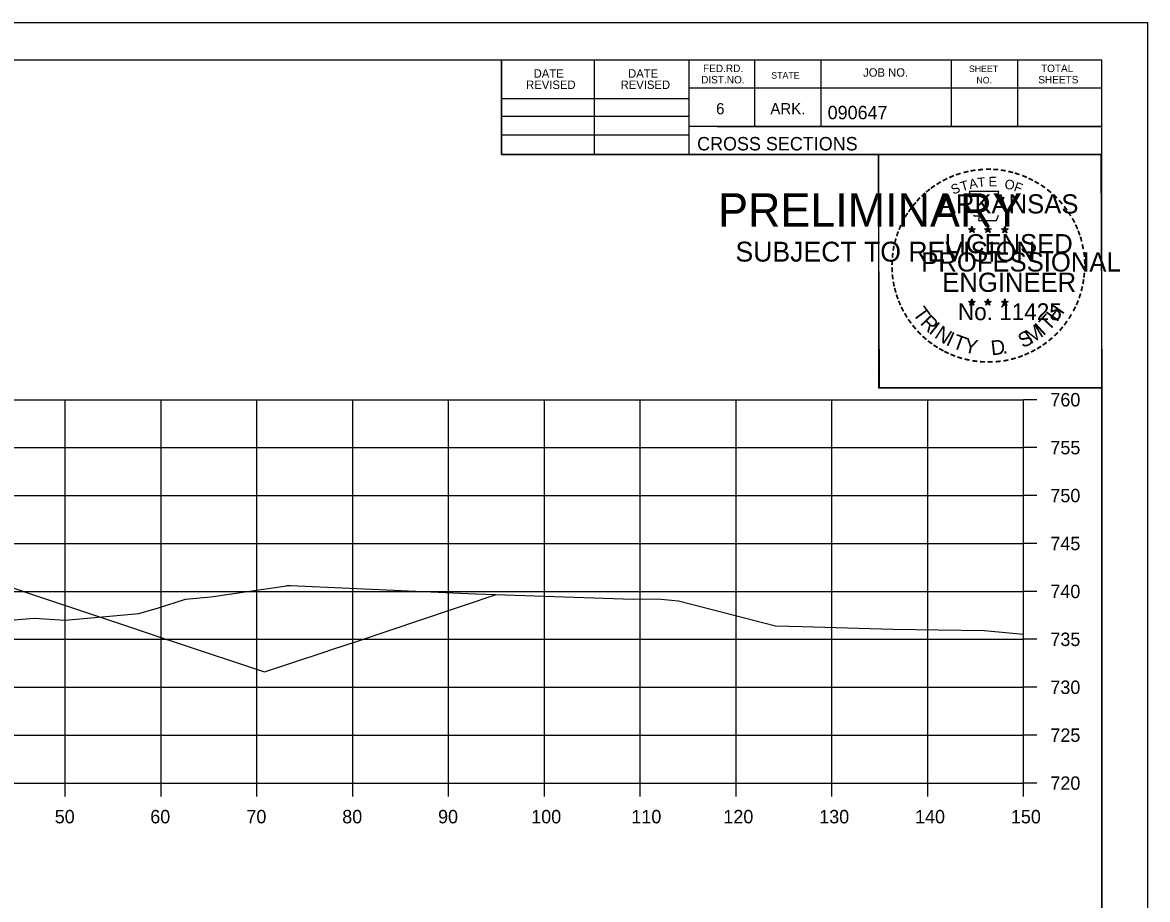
# Model space of a CAD drawing. Extents: x 1202951 to 1376887, y 378065 to 728038.
# Drawn here: x 1374330.5 to 1374447.9, y 379095.1 to 379186.6 of the extents above; entities that cross this region are included whole.
import ezdxf

# ---------------------------------------------------------------- set-up
doc = ezdxf.new("R2010")
doc.units = 0
for name, color, linetype in [('R_Axis', 7, 'Continuous'), ('R_Axis Annot', 7, 'Continuous'), ('R_Exist Surface', 7, 'Continuous'), ('R_Fin Surface', 7, 'Continuous'), ('R_Grid', 7, 'Continuous'), ('R_No Plot', 7, 'Continuous')]:
    doc.layers.add(name, color=color, linetype=linetype)

msp = doc.modelspace()

# ---------------------------------------------------------------- linework, layer by layer
at = {"layer": 'R_Axis'}
for p, q in [((1374434.98, 379107.26), (1374434.98, 379147.26)), ((1374436.38, 379147.26), (1374434.98, 379147.26)), ((1374436.38, 379142.26), (1374434.98, 379142.26)), ((1374436.38, 379137.26), (1374434.98, 379137.26)), ((1374436.38, 379132.26), (1374434.98, 379132.26)), ((1374436.38, 379127.26), (1374434.98, 379127.26)), ((1374436.38, 379122.26), (1374434.98, 379122.26)), ((1374436.38, 379117.26), (1374434.98, 379117.26)), ((1374436.38, 379112.26), (1374434.98, 379112.26)), ((1374134.98, 379107.26), (1374434.98, 379107.26)), ((1374334.98, 379105.86), (1374334.98, 379107.26)), ((1374344.98, 379105.86), (1374344.98, 379107.26)), ((1374354.98, 379105.86), (1374354.98, 379107.26)), ((1374364.98, 379105.86), (1374364.98, 379107.26)), ((1374374.98, 379105.86), (1374374.98, 379107.26)), ((1374384.98, 379105.86), (1374384.98, 379107.26)), ((1374394.98, 379105.86), (1374394.98, 379107.26)), ((1374404.98, 379105.86), (1374404.98, 379107.26)), ((1374414.98, 379105.86), (1374414.98, 379107.26)), ((1374424.98, 379105.86), (1374424.98, 379107.26)), ((1374434.98, 379105.86), (1374434.98, 379107.26)), ((1374436.38, 379107.26), (1374434.98, 379107.26))]:
    msp.add_line(p, q, dxfattribs=at)
at = {"layer": 'R_Exist Surface'}
msp.add_lwpolyline([(1374327.13, 379124.08), (1374331.76, 379124.46), (1374334.98, 379124.26), (1374342.65, 379124.96), (1374344.7, 379125.55), (1374347.52, 379126.45), (1374350.18, 379126.69), (1374358.08, 379127.85), (1374358.16, 379127.86), (1374358.49, 379127.89), (1374370.8, 379127.32), (1374377.81, 379126.99), (1374394.26, 379126.44), (1374396.79, 379126.47), (1374398.99, 379126.28), (1374409.09, 379123.66), (1374411.88, 379123.59), (1374421.33, 379123.32), (1374430.87, 379123.19), (1374434.98, 379122.81)], dxfattribs=at)
at = {"layer": 'R_Fin Surface'}
msp.add_lwpolyline([(1374319.78, 379130.87), (1374341.6, 379123.59), (1374345.29, 379122.36), (1374346.34, 379122.01), (1374355.78, 379118.86), (1374361.9, 379120.9), (1374362.9, 379121.23), (1374365.36, 379122.05), (1374375.6, 379125.47), (1374375.9, 379125.57), (1374376.63, 379125.81), (1374379.96, 379126.92)], dxfattribs=at)
at = {"layer": 'R_Grid'}
for p, q in [((1374134.98, 379147.26), (1374434.98, 379147.26)), ((1374334.98, 379107.26), (1374334.98, 379147.26)), ((1374344.98, 379107.26), (1374344.98, 379147.26)), ((1374354.98, 379107.26), (1374354.98, 379147.26)), ((1374364.98, 379107.26), (1374364.98, 379147.26)), ((1374374.98, 379107.26), (1374374.98, 379147.26)), ((1374384.98, 379107.26), (1374384.98, 379147.26)), ((1374394.98, 379107.26), (1374394.98, 379147.26)), ((1374404.98, 379107.26), (1374404.98, 379147.26)), ((1374414.98, 379107.26), (1374414.98, 379147.26)), ((1374424.98, 379107.26), (1374424.98, 379147.26)), ((1374434.98, 379107.26), (1374434.98, 379147.26)), ((1374134.98, 379142.26), (1374434.98, 379142.26)), ((1374134.98, 379137.26), (1374434.98, 379137.26)), ((1374134.98, 379132.26), (1374434.98, 379132.26)), ((1374134.98, 379127.26), (1374434.98, 379127.26)), ((1374134.98, 379122.26), (1374434.98, 379122.26)), ((1374134.98, 379117.26), (1374434.98, 379117.26)), ((1374134.98, 379112.26), (1374434.98, 379112.26)), ((1374134.98, 379107.26), (1374434.98, 379107.26))]:
    msp.add_line(p, q, dxfattribs=at)
at = {"layer": 'R_No Plot'}
for p, q in [((1374114.58, 379186.62), (1374447.91, 379186.62)), ((1374126.98, 379182.72), (1374443.16, 379182.72)), ((1374380.52, 379172.84), (1374380.52, 379182.72)), ((1374390.2, 379172.84), (1374390.2, 379182.72)), ((1374400.06, 379182.72), (1374400.06, 379172.84)), ((1374406.9, 379182.72), (1374406.9, 379175.78)), ((1374413.84, 379182.72), (1374413.84, 379175.78)), ((1374427.42, 379182.72), (1374427.42, 379175.78)), ((1374434.36, 379182.72), (1374434.36, 379175.78)), ((1374443.16, 378977.26), (1374443.16, 379182.72)), ((1374443.16, 379179.78), (1374400.06, 379179.78)), ((1374443.16, 379179.8), (1374443.16, 379179.8)), ((1374380.52, 379178.7), (1374400.06, 379178.7)), ((1374380.52, 379176.84), (1374400.06, 379176.84)), ((1374443.16, 379175.78), (1374400.06, 379175.78)), ((1374403.02, 379175.78), (1374443.16, 379175.78)), ((1374380.52, 379174.9), (1374400.06, 379174.9)), ((1374443.16, 379172.84), (1374380.52, 379172.84)), ((1374429.24, 379165.1), (1374429.59, 379164.98)), ((1374429.24, 379165.1), (1374429.5, 379165.05)), ((1374429.24, 379165.1), (1374429.48, 379164.97)), ((1374429.38, 379164.69), (1374429.59, 379164.98)), ((1374429.38, 379164.69), (1374429.5, 379164.93)), ((1374429.38, 379164.69), (1374429.59, 379164.9)), ((1374429.59, 379165.35), (1374429.55, 379165.1)), ((1374429.59, 379164.98), (1374429.59, 379165.35)), ((1374429.59, 379165.35), (1374429.64, 379165.1)), ((1374429.94, 379165.1), (1374429.59, 379164.98)), ((1374429.81, 379164.69), (1374429.59, 379164.98)), ((1374429.81, 379164.69), (1374429.59, 379164.9)), ((1374429.94, 379165.1), (1374429.65, 379165.05)), ((1374429.81, 379164.69), (1374429.67, 379164.98)), ((1374429.94, 379165.1), (1374429.74, 379164.99)), ((1374430.91, 379165.1), (1374431.26, 379164.98)), ((1374430.91, 379165.1), (1374431.17, 379165.05)), ((1374430.91, 379165.1), (1374431.15, 379164.97)), ((1374431.05, 379164.69), (1374431.26, 379164.98)), ((1374431.05, 379164.69), (1374431.17, 379164.93)), ((1374431.05, 379164.69), (1374431.26, 379164.9)), ((1374431.26, 379165.35), (1374431.22, 379165.1)), ((1374431.26, 379164.98), (1374431.26, 379165.35)), ((1374431.26, 379165.35), (1374431.31, 379165.1)), ((1374431.61, 379165.1), (1374431.26, 379164.98)), ((1374431.48, 379164.69), (1374431.26, 379164.98)), ((1374431.48, 379164.69), (1374431.26, 379164.9)), ((1374431.61, 379165.1), (1374431.32, 379165.05)), ((1374431.48, 379164.69), (1374431.34, 379164.98)), ((1374431.61, 379165.1), (1374431.41, 379164.99)), ((1374432.68, 379165.08), (1374433.03, 379164.97)), ((1374432.68, 379165.08), (1374432.93, 379165.04)), ((1374432.68, 379165.08), (1374432.92, 379164.96)), ((1374432.81, 379164.68), (1374433.03, 379164.97)), ((1374432.81, 379164.68), (1374432.94, 379164.92)), ((1374432.81, 379164.68), (1374433.03, 379164.89)), ((1374433.03, 379165.34), (1374432.99, 379165.09)), ((1374433.03, 379164.97), (1374433.03, 379165.34)), ((1374433.03, 379165.34), (1374433.08, 379165.09)), ((1374433.37, 379165.08), (1374433.03, 379164.97)), ((1374433.24, 379164.68), (1374433.03, 379164.97)), ((1374433.24, 379164.68), (1374433.03, 379164.89)), ((1374433.37, 379165.08), (1374433.09, 379165.03)), ((1374433.24, 379164.68), (1374433.1, 379164.97)), ((1374433.37, 379165.08), (1374433.17, 379164.98)), ((1374429.24, 379157.52), (1374429.59, 379157.41)), ((1374429.24, 379157.52), (1374429.49, 379157.48)), ((1374429.24, 379157.52), (1374429.48, 379157.4)), ((1374429.37, 379157.11), (1374429.59, 379157.41)), ((1374429.37, 379157.11), (1374429.5, 379157.36)), ((1374429.37, 379157.11), (1374429.59, 379157.33)), ((1374429.59, 379157.78), (1374429.55, 379157.52)), ((1374429.59, 379157.41), (1374429.59, 379157.78)), ((1374429.59, 379157.78), (1374429.64, 379157.53)), ((1374429.94, 379157.52), (1374429.59, 379157.41)), ((1374429.8, 379157.11), (1374429.59, 379157.41)), ((1374429.8, 379157.11), (1374429.59, 379157.33)), ((1374429.94, 379157.52), (1374429.65, 379157.47)), ((1374429.8, 379157.11), (1374429.67, 379157.41)), ((1374429.94, 379157.52), (1374429.73, 379157.42)), ((1374430.91, 379157.52), (1374431.26, 379157.41)), ((1374430.91, 379157.52), (1374431.16, 379157.48)), ((1374430.91, 379157.52), (1374431.15, 379157.4)), ((1374431.04, 379157.11), (1374431.26, 379157.41)), ((1374431.04, 379157.11), (1374431.17, 379157.36)), ((1374431.04, 379157.11), (1374431.26, 379157.33)), ((1374431.26, 379157.78), (1374431.22, 379157.52)), ((1374431.26, 379157.41), (1374431.26, 379157.78)), ((1374431.26, 379157.78), (1374431.31, 379157.53)), ((1374431.61, 379157.52), (1374431.26, 379157.41)), ((1374431.47, 379157.11), (1374431.26, 379157.41)), ((1374431.47, 379157.11), (1374431.26, 379157.33)), ((1374431.61, 379157.52), (1374431.32, 379157.47)), ((1374431.47, 379157.11), (1374431.33, 379157.41)), ((1374431.61, 379157.52), (1374431.4, 379157.42)), ((1374432.68, 379157.51), (1374433.03, 379157.4)), ((1374432.68, 379157.51), (1374432.93, 379157.47)), ((1374432.68, 379157.51), (1374432.91, 379157.39)), ((1374432.81, 379157.1), (1374433.03, 379157.4)), ((1374432.81, 379157.1), (1374432.94, 379157.35)), ((1374432.81, 379157.1), (1374433.02, 379157.32)), ((1374433.03, 379157.77), (1374432.98, 379157.51)), ((1374433.24, 379157.1), (1374433.02, 379157.32)), ((1374433.03, 379157.4), (1374433.03, 379157.77)), ((1374433.03, 379157.77), (1374433.07, 379157.52)), ((1374433.37, 379157.51), (1374433.03, 379157.4)), ((1374433.24, 379157.1), (1374433.03, 379157.4)), ((1374433.37, 379157.51), (1374433.09, 379157.46)), ((1374433.24, 379157.1), (1374433.1, 379157.4)), ((1374433.37, 379157.51), (1374433.17, 379157.41)), ((1374419.19, 379150.39), (1374419.19, 379150.39))]:
    msp.add_line(p, q, dxfattribs=at)
for points in [[(1374114.57, 379186.62), (1374447.91, 379186.62), (1374447.91, 378973.28), (1374114.57, 378973.28)], [(1374360.9, 379182.72), (1374380.52, 379182.72), (1374380.52, 379172.84), (1374396.63, 379172.84), (1374419.83, 379172.84), (1374419.83, 379148.51), (1374443.16, 379148.51), (1374443.16, 378977.26), (1374126.98, 378977.26), (1374126.98, 379182.72)], [(1374419.83, 379172.84), (1374443.04, 379172.84), (1374443.16, 379148.51), (1374419.95, 379148.51)]]:
    msp.add_lwpolyline(points, close=True, dxfattribs=at)
for points in [[(1374429.29, 379168.97), (1374429.55, 379168.15)], [(1374432.8, 379168.05), (1374432.94, 379168.34), (1374432.25, 379168.31), (1374432.4, 379168.97), (1374429.29, 379168.97)], [(1374429.78, 379166.55), (1374429.78, 379166.46), (1374430.34, 379166.44), (1374430.29, 379165.97), (1374432.16, 379165.97), (1374432.36, 379166.51)], [(1374429.59, 379165.35), (1374429.81, 379164.69), (1374429.24, 379165.1), (1374429.94, 379165.1), (1374429.38, 379164.69), (1374429.59, 379165.35)], [(1374431.26, 379165.35), (1374431.48, 379164.69), (1374430.91, 379165.1), (1374431.61, 379165.1), (1374431.05, 379164.69), (1374431.26, 379165.35)], [(1374433.03, 379165.34), (1374433.24, 379164.68), (1374432.68, 379165.08), (1374433.37, 379165.08), (1374432.81, 379164.68), (1374433.03, 379165.34)], [(1374429.59, 379157.78), (1374429.8, 379157.11), (1374429.24, 379157.52), (1374429.94, 379157.52), (1374429.37, 379157.11), (1374429.59, 379157.78)], [(1374431.26, 379157.78), (1374431.47, 379157.11), (1374430.91, 379157.52), (1374431.61, 379157.52), (1374431.04, 379157.11), (1374431.26, 379157.78)], [(1374433.03, 379157.77), (1374433.24, 379157.1), (1374432.68, 379157.51), (1374433.37, 379157.51), (1374432.81, 379157.1), (1374433.03, 379157.77)]]:
    msp.add_lwpolyline(points, dxfattribs=at)
for centre, radius in [((1374429.59, 379164.98), 0.172), ((1374429.59, 379164.98), 0.145), ((1374429.59, 379164.98), 0.116), ((1374429.59, 379164.98), 0.0991), ((1374429.59, 379164.98), 0.0747), ((1374429.59, 379164.98), 0.0495), ((1374429.59, 379164.98), 0.0296), ((1374431.26, 379164.98), 0.172), ((1374431.26, 379164.98), 0.145), ((1374431.26, 379164.98), 0.116), ((1374431.26, 379164.98), 0.0991), ((1374431.26, 379164.98), 0.0747), ((1374431.26, 379164.98), 0.0495), ((1374431.26, 379164.98), 0.0296), ((1374433.03, 379164.97), 0.172), ((1374433.03, 379164.97), 0.145), ((1374433.03, 379164.97), 0.116), ((1374433.03, 379164.97), 0.0991), ((1374433.03, 379164.97), 0.0747), ((1374433.03, 379164.97), 0.0495), ((1374433.03, 379164.97), 0.0296), ((1374429.59, 379157.41), 0.172), ((1374429.59, 379157.41), 0.145), ((1374429.59, 379157.41), 0.116), ((1374429.59, 379157.41), 0.0991), ((1374429.59, 379157.41), 0.0747), ((1374429.59, 379157.41), 0.0495), ((1374429.59, 379157.41), 0.0296), ((1374431.26, 379157.41), 0.172), ((1374431.26, 379157.41), 0.145), ((1374431.26, 379157.41), 0.116), ((1374431.26, 379157.41), 0.0991), ((1374431.26, 379157.41), 0.0747), ((1374431.26, 379157.41), 0.0495), ((1374431.26, 379157.41), 0.0296), ((1374433.02, 379157.4), 0.172), ((1374433.02, 379157.4), 0.145), ((1374433.02, 379157.4), 0.116), ((1374433.02, 379157.4), 0.0991), ((1374433.02, 379157.4), 0.0747), ((1374433.02, 379157.4), 0.0495), ((1374433.02, 379157.4), 0.0296)]:
    msp.add_circle(centre, radius, dxfattribs=at)

# ---------------------------------------------------------------- texts
at = {"layer": 'R_Axis Annot'}
for s, p in [('760', (1374437.78, 379146.56)), ('755', (1374437.78, 379141.56)), ('750', (1374437.78, 379136.56)), ('745', (1374437.78, 379131.56)), ('740', (1374437.78, 379126.56)), ('735', (1374437.78, 379121.56)), ('730', (1374437.78, 379116.56)), ('725', (1374437.78, 379111.56)), ('720', (1374437.78, 379106.56)), ('50', (1374333.89, 379103.06)), ('60', (1374343.86, 379103.06)), ('70', (1374353.89, 379103.06)), ('80', (1374363.89, 379103.06)), ('90', (1374373.89, 379103.06)), ('100', (1374383.61, 379103.06)), ('110', (1374394.06, 379103.06)), ('120', (1374403.66, 379103.06)), ('130', (1374413.66, 379103.06)), ('140', (1374423.66, 379103.06)), ('150', (1374433.66, 379103.06))]:
    msp.add_text(s, height=1.4, dxfattribs=at).set_placement(p)
at = {"layer": 'R_No Plot'}
for s, height, rotation, p in [('DATE', 0.879, 360, (1374383.86, 379180.86)), ('DATE', 0.879, 360, (1374393.72, 379180.86)), ('FED.RD.', 0.782, 360, (1374401.54, 379181.44)), ('STATE', 0.684, 360, (1374408.66, 379180.76)), ('JOB NO.', 0.879, 360, (1374418.24, 379180.96)), ('SHEET', 0.684, 360, (1374429.28, 379181.44)), ('TOTAL', 0.782, 360, (1374436.8, 379181.44)), ('REVISED', 0.879, 360, (1374383.08, 379179.68)), ('REVISED', 0.879, 360, (1374392.94, 379179.68)), ('DIST.NO.', 0.782, 360, (1374401.34, 379180.26)), ('NO.', 0.684, 360, (1374430.06, 379180.26)), ('SHEETS', 0.782, 360, (1374436.52, 379180.26)), ('6', 1.17, 360, (1374402.9, 379177.04)), ('ARK.', 1.172, 360, (1374408.56, 379177.04)), ('090647', 1.4, 360, (1374414.54, 379176.52)), ('CROSS SECTIONS', 1.4, 360, (1374400.92, 379173.27)), ('-', 1.6, 19.1761, (1374428.03, 379170.1)), ('-', 1.6, 13.6301, (1374428.78, 379170.34)), ('-', 1.6, 10.2193, (1374429.46, 379170.5)), ('-', 1.6, 5.8968, (1374430.19, 379170.61)), ('-', 1.6, 0.1862, (1374430.96, 379170.69)), ('-', 1.6, 357.743, (1374431.69, 379170.67)), ('-', 1.6, 352.1617, (1374432.43, 379170.62)), ('-', 1.6, 347.2049, (1374433.15, 379170.5)), ('-', 1.6, 342.3362, (1374433.78, 379170.35)), ('-', 1.6, 337.8551, (1374434.52, 379170.12)), ('-', 1.6, 36.2317, (1374425.59, 379168.75)), ('-', 1.6, 34.0636, (1374426.17, 379169.14)), ('-', 1.6, 28.7918, (1374426.77, 379169.51)), ('-', 1.6, 24.3072, (1374427.4, 379169.83)), ('S', 1, 21.594, (1374427.64, 379168.65)), ('T', 1, 16.4036, (1374428.55, 379168.98)), ('A', 1, 11.2132, (1374429.38, 379169.23)), ('T', 1, 6.0228, (1374430.23, 379169.4)), ('E', 1, 0.8323, (1374431.33, 379169.51)), ('O', 1, 350.4515, (1374432.94, 379169.3)), ('F', 1, 340.0707, (1374433.89, 379169.07)), ('-', 1.6, 334.1211, (1374435.15, 379169.85)), ('-', 1.6, 329.6409, (1374435.73, 379169.57)), ('-', 1.6, 325.8627, (1374436.37, 379169.21)), ('PRELIMINARY', 3.5, 360, (1374403.11, 379165.3)), ('-', 1.6, 48.423, (1374424.23, 379167.48)), ('-', 1.6, 42.9622, (1374424.68, 379167.95)), ('-', 1.6, 38.9507, (1374425.12, 379168.37)), ('ARKANSAS', 2, 360, (1374426.14, 379166.69)), ('-', 1.6, 320.5297, (1374436.98, 379168.78)), ('-', 1.6, 315.5786, (1374437.58, 379168.3)), ('-', 1.6, 54.2325, (1374423.42, 379166.42)), ('-', 1.6, 50.6142, (1374423.83, 379166.99)), ('-', 1.6, 309.8797, (1374438.15, 379167.75)), ('-', 1.6, 306.6522, (1374438.67, 379167.14)), ('DWB', 0.01, 360, (1374403.86, 379167.15)), ('-', 1.6, 62.8713, (1374422.78, 379165.28)), ('-', 1.6, 58.0706, (1374423.09, 379165.9)), ('-', 1.4, 303.6753, (1374439.16, 379166.58)), ('-', 1.6, 299.6684, (1374439.48, 379165.97)), ('-', 1.6, 67.7743, (1374422.52, 379164.67)), ('DWB', 0.01, 360, (1374429.58, 379164.98)), ('DWB', 0.01, 360, (1374431.25, 379164.98)), ('DWB', 0.01, 360, (1374433.02, 379164.97)), ('-', 1.6, 294.6628, (1374439.8, 379165.36)), ('-', 1.6, 290.5728, (1374440.06, 379164.78)), ('SUBJECT TO REVISION', 2.0751, 360, (1374404.92, 379161.67)), ('-', 1.6, 75.461, (1374422.11, 379163.33)), ('-', 1.6, 72.3945, (1374422.3, 379164.04)), ('LICENSED', 2, 360, (1374426.74, 379162.54)), ('-', 1.6, 285.1233, (1374440.29, 379164.2)), ('-', 1.6, 85.1863, (1374421.9, 379161.92)), ('-', 1.6, 81.2013, (1374421.97, 379162.61)), ('PROFESSIONAL', 2, 360, (1374424.31, 379160.63)), ('-', 1.6, 280.5493, (1374440.49, 379163.46)), ('-', 1.6, 276.5962, (1374440.66, 379162.69)), ('-', 1.6, 89.0622, (1374421.87, 379161.22)), ('-', 1.6, 274.3301, (1374440.72, 379161.97)), ('-', 1.6, 94.1959, (1374421.91, 379160.5)), ('-', 1.6, 98.9479, (1374421.98, 379159.83)), ('ENGINEER', 2, 360, (1374426.5, 379158.51)), ('-', 1.6, 263.5172, (1374440.73, 379160.67)), ('-', 1.6, 269.9407, (1374440.75, 379161.34)), ('-', 1.6, 101.7149, (1374422.11, 379159.1)), ('-', 1.6, 255.7626, (1374440.55, 379159.34)), ('-', 1.6, 260.9953, (1374440.66, 379160.02)), ('-', 1.6, 105.4578, (1374422.28, 379158.5)), ('-', 1.6, 109.0874, (1374422.49, 379157.87)), ('-', 1.6, 252.8681, (1374440.37, 379158.62)), ('-', 1.6, 114.0643, (1374422.75, 379157.28)), ('-', 1.6, 115.7289, (1374423.05, 379156.66)), ('T', 1.54, 306.0406, (1374423.35, 379156.25)), ('No. 11425', 1.757, 360, (1374428.13, 379155.56)), ('DWB', 0.01, 360, (1374429.58, 379157.41)), ('DWB', 0.01, 360, (1374431.25, 379157.41)), ('DWB', 0.01, 360, (1374433.01, 379157.4)), ('H', 1.54, 54.6088, (1374438.47, 379155.29)), ('-', 1.6, 244.6197, (1374439.88, 379157.32)), ('-', 1.6, 247.8887, (1374440.15, 379157.94)), ('-', 1.6, 120.4471, (1374423.41, 379156.07)), ('-', 1.6, 125.8934, (1374423.81, 379155.51)), ('R', 1.54, 314.005, (1374424.11, 379155.2)), ('T', 1.54, 46.6444, (1374437.58, 379154.34)), ('-', 1.6, 233.8452, (1374439.09, 379155.91)), ('-', 1.6, 239.0712, (1374439.49, 379156.56)), ('-', 1.6, 130.7181, (1374424.27, 379154.96)), ('-', 1.6, 134.2238, (1374424.79, 379154.41)), ('I', 1.54, 321.9694, (1374425.01, 379154.27)), ('N', 1.54, 326.5002, (1374425.58, 379153.8)), ('I', 1.54, 335.3603, (1374426.79, 379153.01)), ('S', 1.54, 26.9312, (1374434.9, 379152.61)), ('M', 1.54, 32.6563, (1374435.73, 379153.02)), ('I', 1.54, 42.1136, (1374437.02, 379153.86)), ('-', 1.6, 225.7653, (1374438.18, 379154.78)), ('-', 1.6, 231.2538, (1374438.66, 379155.34)), ('-', 1.6, 138.9338, (1374425.31, 379153.95)), ('-', 1.6, 144.6463, (1374425.87, 379153.54)), ('T', 1.54, 339.8912, (1374427.45, 379152.69)), ('Y', 1.54, 347.8556, (1374428.67, 379152.24)), ('D', 1.54, 6.3969, (1374431.65, 379151.88)), ('-', 1.6, 215.7363, (1374437.11, 379153.8)), ('-', 1.6, 221.0851, (1374437.66, 379154.27)), ('-', 1.6, 148.0898, (1374426.43, 379153.17)), ('-', 1.6, 151.5704, (1374427.01, 379152.85)), ('-', 1.6, 154.6002, (1374427.53, 379152.6)), ('-', 1.6, 158.5612, (1374428.16, 379152.35)), ('.', 1.54, 13.7642, (1374432.84, 379152.01)), ('-', 1.6, 204.2516, (1374435.39, 379152.75)), ('-', 1.6, 207.3568, (1374436.02, 379153.07)), ('-', 1.6, 212.2491, (1374436.57, 379153.41)), ('-', 1.6, 162.7983, (1374428.84, 379152.13)), ('-', 1.6, 167.5555, (1374429.56, 379151.97)), ('-', 1.6, 173.1155, (1374430.33, 379151.86)), ('-', 1.6, 176.5183, (1374431.08, 379151.81)), ('-', 1.6, 181.5918, (1374431.82, 379151.83)), ('-', 1.6, 185.8167, (1374432.63, 379151.9)), ('-', 1.6, 191.2858, (1374433.37, 379152.03)), ('-', 1.6, 195.4743, (1374434.1, 379152.23)), ('-', 1.6, 200.7184, (1374434.77, 379152.47))]:
    msp.add_text(s, height=height, rotation=rotation, dxfattribs=at).set_placement(p)

doc.saveas('drawing.dxf')
